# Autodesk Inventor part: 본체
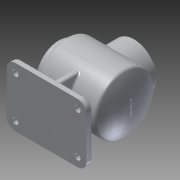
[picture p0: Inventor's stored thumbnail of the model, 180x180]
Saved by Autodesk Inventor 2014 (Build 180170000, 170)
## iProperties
Created: 2016-09
Part Number: 본체
Material: 알루미늄 6061
Document SubType Name: Modeling
Designer: 702
Density: 2.71 g/cm^3
Appearance: 알루미늄 - 평지
Author: 702
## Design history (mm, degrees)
sketch "스케치1"
  geometry: L1 (115, 0)-(5, 0); L2 (5, 0)-(5, 50); L3 (5, 50)-(103.562, 50); A1 r 115 centre (0, 0) between (115, 0) and (103.562, 50)
  constraints: 6 end point, 2 point on circle, 1 centre point, 1 horizontal, 1 parallel, 1 perpendicular
  dimensions: "d6" = 230 diameter of A1; "d7" = 110 distance of L1.start L1.end; "d8" = 50 distance of L1.end L2.end
revolve "회전1" sketch "스케치1" stored, may be unused: angle "d9" = 90 deg
sketch "스케치2"
  geometry: C1 r 50 at (0, 0) reference; C2 r 38 at (0, 0)
  constraints: 1 centre point, 1 coincident
  dimensions: "d10" = 76 diameter of C2
extrude "돌출1" join sketch "스케치2" distance "d11" = 12; taper "d12" = 0 deg
sketch "스케치3"
  geometry: C1 r 38 at (0, 0) reference; C2 r 27 at (0, 0)
  constraints: 1 centre point, 1 coincident
  dimensions: "d13" = 54 diameter of C2
extrude "돌출2" cut sketch "스케치3" distance "d14" = 15; taper "d15" = 0 deg
sketch "스케치5"
  geometry: L1 (5, -50)-(5, 50) reference; L2 (103.562, -50)-(103.562, 50) reference; L3 (103.562, -50)-(103.562, 50) reference; L4 (114.677, 0)-(111.677, 0); L5 (111.677, 0)-(8, 0); L6 (103.562, 50)-(103.562, 47); L7 (5, 50)-(8, 50); L8 (8, 50)-(8, 47); L9 (8, 47)-(101.634, 47); L10 (5, -50)-(8, -50); L11 (8, -50)-(8, -47); L12 (8, 0)-(8, 47); A1 r 115 centre (-3.323, 0) between (111.677, 0) and (101.634, 47); 1 further point
  constraints: 18 end point, 4 perpendicular, 2 parallel, 2 point on circle, 1 centre point, 1 collinear, 1 point on line
  dimensions: "d16" = 3 distance of L4.start L4.end; "d18" = 3 distance of L3.end L6.end; "d19" = 3 distance of L1.end L7.end; "d20" = 3 distance of L7.end L8.end; "d21" = 3 distance of L1.start L10.end; "d22" = 3 distance of L10.end L11.end
revolve "회전2" sketch "스케치5" stored, may be unused: angle "d23" = 90 deg
sketch "스케치6"
  geometry: 1 further point
node "작업 평면1"
sketch "스케치9"
  geometry: 1 further point
node "작업 평면2"
sketch "스케치10"
  geometry: L1 (-103.562, 50)-(-103.562, -50) reference; L2 (-5, 50)-(-5, -50) reference; 1 further point
  node "투영된 루프4"
sketch "스케치11" dims "d117" = 3
  geometry: L1 (-5, 50)-(-5, -50) reference; L2 (-60, 0)-(-60, 50); L3 (-115, 0)-(-60, 0); L4 (-60, 50)-(-127.5, 50); L5 (-127.5, 50)-(-127.5, -50); L6 (-127.5, -50)-(7.5, -50); L7 (7.5, -50)-(7.5, 50); L8 (7.5, 50)-(-60, 50); A1 r 115 centre (3.323, 0) between (-101.634, 47) and (-101.634, -47) reference; A2 r 115 centre (0, 0) between (-103.562, 50) and (-103.562, -50) reference; 1 further point
  constraints: 14 end point, 3 perpendicular, 2 parallel, 1 point on circle
  dimensions: "d34" = 50 distance of L2.start L2.end; "d36" = 55 distance of L3.start L2.start; "d37" = 67.5 distance of L2.end L4.end; "d38" = 100 distance of L4.end L5.end; "d39" = 135 distance of L5.end L6.end; "d40" = 100 distance of L6.end L7.end
sketch "스케치12"
  geometry: L1 (-103.562, 50)-(-103.562, -50) reference; L2 (-5, 50)-(-5, -50) reference; L3 (7, -38)-(7, 38) reference; L4 (7, 0)-(-54, 0); L5 (-54, 0)-(-54, 50); L6 (-54, 50)-(13.5, 50); L7 (13.5, 50)-(13.5, -50); L8 (13.5, -50)-(-121.5, -50); L9 (-121.5, -50)-(-121.5, 50); L10 (-121.5, 50)-(-54, 50); A1 r 115 centre (0, 0) between (-103.562, 50) and (-103.562, -50) reference; 1 further point
  constraints: 14 end point, 4 parallel, 2 perpendicular, 1 midpoint
  dimensions: "d43" = 61 distance of L4.start L4.end; "d44" = 50 distance of L4.end L5.end; "d45" = 67.5 distance of L5.end L6.end; "d46" = 100 distance of L6.end L7.end; "d47" = 135 distance of L7.end L8.end; "d48" = 100 distance of L8.end L9.end
extrude "돌출5" join sketch "스케치12" distance "d49" = 10; taper "d50" = 0 deg
fillet "모깎기1" dims "d69" = 15
sketch "스케치17"
  geometry: L1 (14, -5)-(14, 5) reference; L2 (14, 5)-(94, 5) reference; L3 (54, -5)-(14, -5) reference; L4 (94, -5)-(54, -5) reference; L5 (94, 5)-(94, -5) reference; L6 (14, 5)-(94, 5); L7 (94, -5)-(14, -5); L8 (54, 45)-(49, 45); L9 (54, 0)-(54, 40); L10 (54, 40)-(49, 40); L11 (49, 40)-(49, -40); L12 (49, -40)-(59, -40); L13 (59, -40)-(59, 40); L14 (59, 40)-(49, 40); 1 further point
  constraints: 18 end point, 5 perpendicular, 1 collinear, 1 parallel
  dimensions: "d73" = 5 distance of L8.start L8.end; "d75" = 40 distance of L9.start L9.end; "d76" = 5 distance of L9.end L10.end; "d77" = 80 distance of L10.end L11.end; "d78" = 10 distance of L11.end L12.end; "d79" = 80 distance of L12.end L13.end
extrude "돌출9" join sketch "스케치17" stored distance "d80" = 10; taper "d81" = 0 deg
sketch "스케치18"
  geometry: L1 (0, 22.251)-(35, 22.251) reference; L2 (0, 0)-(0, 22.251) reference; L3 (35, 0)-(0, 0) reference; L4 (35, 0)-(35, 22.251) reference; 1 further point
fillet "모깎기4" dims "d82" = 3
sketch "스케치19"
  geometry: C1 r 5 at (1.5, 35); C2 r 5 at (1.5, -35); C3 r 5 at (106.5, -35); C4 r 5 at (106.5, 35); A1 r 15 centre (106.5, 35) between (121.5, 35) and (106.5, 50) reference; A2 r 15 centre (1.5, 35) between (1.5, 50) and (-13.5, 35) reference; A3 r 15 centre (1.5, -35) between (-13.5, -35) and (1.5, -50) reference; A4 r 15 centre (106.5, -35) between (106.5, -50) and (121.5, -35) reference; 1 further point
  constraints: 4 centre point, 4 coincident
  dimensions: "d84" = 10 diameter of C1; "d85" = 10 diameter of C2; "d86" = 10 diameter of C3; "d87" = 10 diameter of C4
extrude "돌출10" cut sketch "스케치19" distance "d88" = 100; taper "d89" = 0 deg
sketch "스케치20"
  geometry: C1 r 38 at (0, 0) reference; A1 r 32.5 centre (0, 0) between (0, 32.5) and (-32.5, 0); 2 further points
  constraints: 4 point on circle, 1 centre point, 1 coincident
  dimensions: "d90" = 65 diameter of A1
hole "구멍1" sketch "스케치20" at (32.5, 0), (0, 32.5), (-32.5, 0), (0, -32.5) diameter "d91" = 3.242; stored, may be unused: countersink angle "d95" = 90 deg, drill point angle "d97" = 118 deg; dims "d92" = 8, "d93" = 4, "d94" = 2, "d96" = 10
chamfer "모따기1" distance "d106" = 1; stored, may be unused: second distance "d107" = 2, angle "d108" = 45 deg
fillet "모깎기5" dims "d109" = 5
fillet "모깎기6" dims "d110" = 3
fillet "모깎기7" dims "d111" = 2
fillet "모깎기8" dims "d112" = 3
node "작업 평면3"
sketch "스케치22"
  geometry: 2 further points
  constraints: 1 coincident, 1 other
feature "엠보싱1" sketch "스케치22" dims "d6" = 230, "d7" = 110, "d8" = 50, "d114" = 0.5, "d115" = 0
fillet "모깎기9" dims "d116" = 3
fillet "모깎기10" dims "d117" = 3
node "작업 평면4"
sketch "스케치23"
  geometry: L1 (-10, -50)-(-10, 50) reference; L2 (-62, 7.547)-(-62, 34.906) reference; L3 (-91, 7.547)-(-62, 7.547) reference; L4 (-97, -1.887)-(-97, 1.887) reference; L5 (-62, -7.547)-(-91, -7.547) reference; L6 (-62, -34.906)-(-62, -7.547) reference; L7 (-46, -40.566)-(-56, -40.566) reference; L8 (-46, -7.547)-(-46, -40.566) reference; L9 (-11, -7.547)-(-46, -7.547) reference; L10 (-11, 1.887)-(-11, -7.547) reference; L11 (-46, 7.547)-(-17, 7.547) reference; L12 (-46, 34.906)-(-46, 7.547) reference; L13 (-56, 40.566)-(-52, 40.566) reference; L14 (-100.374, 50)-(-100.374, -50) reference; L15 (-5, 45)-(-5, -45) reference; L16 (-5, 0)-(-55, 0); C1 r 38 at (-55, 0); 7 further points
  constraints: 2 end point, 1 centre point, 1 coincident, 1 midpoint, 1 perpendicular, 12 other
  dimensions: "d119" = 50 distance of L16.start L16.end; "d120" = 76 diameter of C1
extrude "돌출11" join sketch "스케치23" stored distance "d121" = 10; taper "d122" = 0 deg
sketch "스케치24"
  geometry: C1 r 38 at (0, 0) reference; C2 r 27 at (0, 0); 1 further point
  constraints: 1 centre point, 1 coincident
  dimensions: "d123" = 54 diameter of C2
extrude "돌출12" cut sketch "스케치24" distance "d124" = 50; taper "d125" = 0 deg
sketch "스케치25"
  geometry: C1 r 38 at (0, 0) reference; A1 r 32.5 centre (0, 0) between (0, 32.5) and (-32.5, 0); 3 further points
  constraints: 4 point on circle, 1 centre point, 1 coincident
  dimensions: "d126" = 65 diameter of A1
hole "구멍3" sketch "스케치25" at (32.5, 0), (0, 32.5), (0, -32.5), (-32.5, 0) diameter "d127" = 3.242; stored, may be unused: countersink angle "d131" = 90 deg, drill point angle "d133" = 118 deg; dims "d128" = 8, "d129" = 4, "d130" = 2, "d132" = 10
fillet "모깎기11" dims "d134" = 3
chamfer "모따기2" distance "d135" = 1; stored, may be unused: second distance "d136" = 2, angle "d137" = 45 deg
node "솔리드1"
node "투영된 루프1"
node "투영된 루프2"
node "투영된 루프5"
node "투영된 루프8"
other parameters: "d24" = 65, "d32" = -82, "d118" = 65
